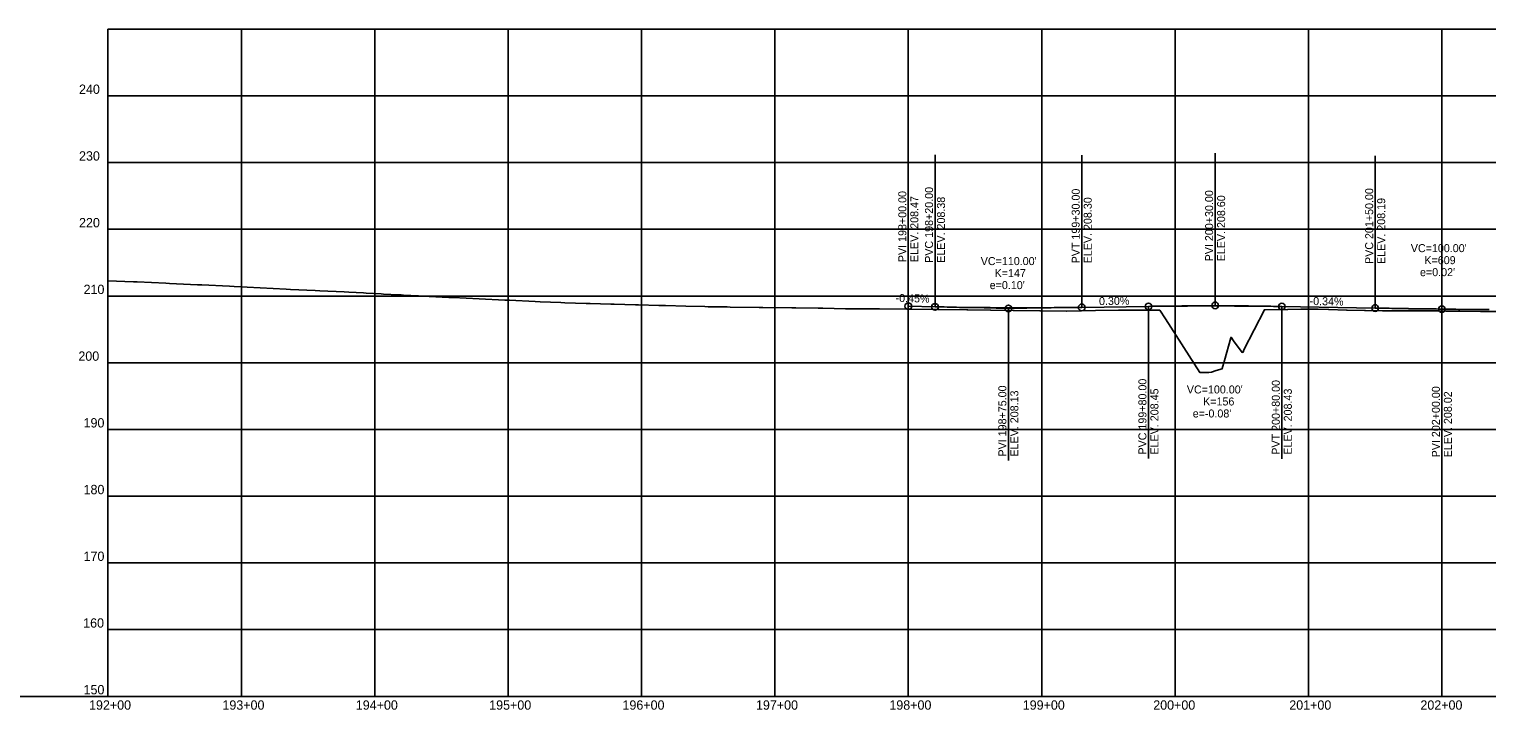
# Model space of a CAD drawing. Extents: x 1138442 to 1165793, y 1654070 to 1657687.
# Drawn here: x 1148047 to 1149139, y 1655756 to 1656266 of the extents above; entities that cross this region are included whole.
import ezdxf

# ---------------------------------------------------------------- set-up
doc = ezdxf.new("R2010")
doc.units = 0
for name, color, linetype in [('B_Dimensions', 7, 'Continuous'), ('R_Axis', 7, 'Continuous'), ('R_Axis Annot', 7, 'Continuous'), ('R_Grid', 7, 'Continuous'), ('R_No Plot', 7, 'Continuous'), ('R_Proposed Const Limits_Hand', 7, 'Continuous'), ('R_Vert Alg Annot', 7, 'Continuous')]:
    doc.layers.add(name, color=color, linetype=linetype)

msp = doc.modelspace()

# ---------------------------------------------------------------- linework, layer by layer
at = {"layer": 'B_Dimensions'}
for p, q in [((1148705.7, 1656058.8), (1148725.7, 1656058.3)), ((1148753.2, 1656057.7), (1148780.7, 1656057.1)), ((1148780.7, 1656057.1), (1148808.2, 1656057.5)), ((1148835.7, 1656057.9), (1148885.7, 1656058.6)), ((1148910.7, 1656059), (1148935.7, 1656059.4)), ((1148935.7, 1656059.4), (1148960.7, 1656059)), ((1148985.7, 1656058.5), (1149055.7, 1656057.4)), ((1149080.7, 1656056.9), (1149105.7, 1656056.5)), ((1149105.7, 1656056.5), (1149130.7, 1656056.3))]:
    msp.add_line(p, q, dxfattribs=at)
for points in [[(1148725.7, 1656058.3), (1148728, 1656058.3), (1148730.3, 1656058.2), (1148732.6, 1656058.2), (1148734.9, 1656058.1), (1148737.2, 1656058.1), (1148739.5, 1656058), (1148741.7, 1656058), (1148744, 1656057.9), (1148746.3, 1656057.9), (1148748.6, 1656057.9), (1148750.9, 1656057.8), (1148753.2, 1656057.8), (1148755.5, 1656057.8), (1148757.8, 1656057.8), (1148760.1, 1656057.7), (1148762.4, 1656057.7), (1148764.7, 1656057.7), (1148767, 1656057.7), (1148769.2, 1656057.6), (1148771.5, 1656057.6), (1148773.8, 1656057.6), (1148776.1, 1656057.6), (1148778.4, 1656057.6), (1148783, 1656057.6), (1148785.3, 1656057.6), (1148787.6, 1656057.6), (1148789.9, 1656057.6), (1148792.2, 1656057.6), (1148794.5, 1656057.6), (1148796.7, 1656057.6), (1148799, 1656057.6), (1148801.3, 1656057.6), (1148803.6, 1656057.6), (1148805.9, 1656057.6), (1148808.2, 1656057.6), (1148810.5, 1656057.6), (1148812.8, 1656057.6), (1148815.1, 1656057.7), (1148817.4, 1656057.7), (1148819.7, 1656057.7), (1148822, 1656057.7), (1148824.2, 1656057.7), (1148826.5, 1656057.8), (1148828.8, 1656057.8), (1148831.1, 1656057.8), (1148833.4, 1656057.9), (1148835.7, 1656057.9)], [(1148885.7, 1656058.6), (1148887.8, 1656058.7), (1148889.9, 1656058.7), (1148892, 1656058.7), (1148894, 1656058.8), (1148896.1, 1656058.8), (1148898.2, 1656058.8), (1148900.3, 1656058.8), (1148902.4, 1656058.8), (1148904.5, 1656058.9), (1148906.5, 1656058.9), (1148908.6, 1656058.9), (1148910.7, 1656058.9), (1148912.8, 1656058.9), (1148914.9, 1656058.9), (1148917, 1656059), (1148919, 1656059), (1148921.1, 1656059), (1148923.2, 1656059), (1148925.3, 1656059), (1148927.4, 1656059), (1148929.5, 1656059), (1148931.5, 1656059), (1148933.6, 1656059), (1148937.8, 1656059), (1148939.9, 1656059), (1148942, 1656059), (1148944, 1656059), (1148946.1, 1656059), (1148948.2, 1656059), (1148950.3, 1656058.9), (1148952.4, 1656058.9), (1148954.5, 1656058.9), (1148956.5, 1656058.9), (1148958.6, 1656058.9), (1148960.7, 1656058.9), (1148962.8, 1656058.8), (1148964.9, 1656058.8), (1148967, 1656058.8), (1148969, 1656058.8), (1148971.1, 1656058.8), (1148973.2, 1656058.7), (1148975.3, 1656058.7), (1148977.4, 1656058.7), (1148979.5, 1656058.6), (1148981.5, 1656058.6), (1148983.6, 1656058.6), (1148985.7, 1656058.5)], [(1149055.7, 1656057.4), (1149057.8, 1656057.3), (1149059.9, 1656057.3), (1149062, 1656057.2), (1149064, 1656057.2), (1149066.1, 1656057.2), (1149068.2, 1656057.1), (1149070.3, 1656057.1), (1149072.4, 1656057.1), (1149074.5, 1656057), (1149076.5, 1656057), (1149078.6, 1656057), (1149080.7, 1656057), (1149082.8, 1656056.9), (1149084.9, 1656056.9), (1149087, 1656056.9), (1149089, 1656056.8), (1149091.1, 1656056.8), (1149093.2, 1656056.8), (1149095.3, 1656056.7), (1149097.4, 1656056.7), (1149099.5, 1656056.7), (1149101.5, 1656056.7), (1149103.6, 1656056.6), (1149107.8, 1656056.6), (1149109.9, 1656056.6), (1149112, 1656056.5), (1149114, 1656056.5), (1149116.1, 1656056.5), (1149118.2, 1656056.4), (1149120.3, 1656056.4), (1149122.4, 1656056.4), (1149124.5, 1656056.4), (1149126.5, 1656056.4), (1149128.6, 1656056.3), (1149130.7, 1656056.3), (1149132.8, 1656056.3), (1149134.9, 1656056.3), (1149137, 1656056.2), (1149139, 1656056.2), (1149141.1, 1656056.2)]]:
    msp.add_lwpolyline(points, dxfattribs=at)
at = {"layer": 'R_Axis'}
for q in [(1148105.7, 1656266.4), (1149805.7, 1655766.4)]:
    msp.add_line((1148105.7, 1655766.4), q, dxfattribs=at)
at = {"layer": 'R_Grid'}
for p, q in [((1148105.7, 1656266.4), (1149805.7, 1656266.4)), ((1148105.7, 1656266.4), (1149805.7, 1656266.4)), ((1148205.7, 1655766.4), (1148205.7, 1656266.4)), ((1148305.7, 1655766.4), (1148305.7, 1656266.4)), ((1148405.7, 1655766.4), (1148405.7, 1656266.4)), ((1148505.7, 1655766.4), (1148505.7, 1656266.4)), ((1148605.7, 1655766.4), (1148605.7, 1656266.4)), ((1148705.7, 1655766.4), (1148705.7, 1656266.4)), ((1148805.7, 1655766.4), (1148805.7, 1656266.4)), ((1148905.7, 1655766.4), (1148905.7, 1656266.4)), ((1149005.7, 1655766.4), (1149005.7, 1656266.4)), ((1149105.7, 1655766.4), (1149105.7, 1656266.4)), ((1148105.7, 1656216.4), (1149805.7, 1656216.4)), ((1148105.7, 1656166.4), (1149805.7, 1656166.4)), ((1148105.7, 1656116.4), (1149805.7, 1656116.4)), ((1148105.7, 1656066.4), (1149805.7, 1656066.4)), ((1148105.7, 1656016.4), (1149805.7, 1656016.4)), ((1148105.7, 1655966.4), (1149805.7, 1655966.4)), ((1148105.7, 1655916.4), (1149805.7, 1655916.4)), ((1148105.7, 1655866.4), (1149805.7, 1655866.4)), ((1148105.7, 1655816.4), (1149805.7, 1655816.4))]:
    msp.add_line(p, q, dxfattribs=at)
at = {"layer": 'R_No Plot'}
msp.add_line((1148105.7, 1655766.4), (1146536.5, 1655766.4), dxfattribs=at)
at = {"layer": 'R_Proposed Const Limits_Hand'}
msp.add_lwpolyline([(1148105.7, 1656077.9), (1148124.8, 1656077.1), (1148127.7, 1656077), (1148149, 1656076), (1148151.7, 1656075.9), (1148172.9, 1656074.9), (1148176, 1656074.8), (1148196.9, 1656073.8), (1148200.4, 1656073.6), (1148219.7, 1656072.5), (1148239.3, 1656071.5), (1148242.5, 1656071.3), (1148261.1, 1656070.5), (1148264.4, 1656070.3), (1148282.7, 1656069.5), (1148286.3, 1656069.3), (1148297.3, 1656068.7), (1148299.3, 1656068.6), (1148310.4, 1656068), (1148312.3, 1656067.9), (1148323.5, 1656067.3), (1148325.4, 1656067.2), (1148327.3, 1656067.1), (1148338.4, 1656066.5), (1148341.6, 1656066.4), (1148361.2, 1656065.4), (1148364.5, 1656065.3), (1148384, 1656064.3), (1148403.3, 1656063.4), (1148406.8, 1656063.2), (1148426, 1656062.3), (1148429.6, 1656062.1), (1148445.3, 1656061.6), (1148448.3, 1656061.4), (1148464.1, 1656060.9), (1148467.1, 1656060.8), (1148482.8, 1656060.3), (1148485.2, 1656060.2), (1148501.2, 1656059.8), (1148503.3, 1656059.7), (1148518.7, 1656059.3), (1148521.2, 1656059.2), (1148523.6, 1656059.2), (1148539, 1656058.7), (1148553.1, 1656058.5), (1148555.6, 1656058.4), (1148570, 1656058.2), (1148572.1, 1656058.1), (1148593.8, 1656057.8), (1148596.7, 1656057.8), (1148618.4, 1656057.5), (1148621.3, 1656057.5), (1148638.2, 1656057.2), (1148640, 1656057.2), (1148641.7, 1656057.2), (1148658.7, 1656056.9), (1148659.6, 1656056.9), (1148682.3, 1656056.8), (1148683.1, 1656056.8), (1148684, 1656056.8), (1148706.7, 1656056.6), (1148707.6, 1656056.6), (1148727.8, 1656056.3), (1148728.9, 1656056.3), (1148749.5, 1656056), (1148750.2, 1656056), (1148767.2, 1656055.8), (1148767.2, 1656055.8), (1148767.5, 1656055.8), (1148784.4, 1656055.5), (1148785, 1656055.5), (1148804.3, 1656055.3), (1148804.8, 1656055.3), (1148824.2, 1656055.1), (1148824.6, 1656055.1), (1148845.9, 1656055.5), (1148846.1, 1656055.5), (1148863.3, 1656055.7), (1148867.6, 1656055.8), (1148867.6, 1656055.8), (1148880.8, 1656055.9), (1148880.9, 1656055.9), (1148894.1, 1656055.9), (1148894.1, 1656055.9), (1148894.2, 1656055.9), (1148898.5, 1656049.2), (1148924.3, 1656009.1), (1148924.4, 1656009.1), (1148931, 1656009.2), (1148933, 1656009.3), (1148933, 1656009.3), (1148936.6, 1656010.5), (1148941.1, 1656011.9), (1148941.1, 1656012), (1148942.8, 1656018), (1148947.6, 1656035), (1148947.7, 1656035.5), (1148949.4, 1656032.9), (1148955.9, 1656024.1), (1148956.7, 1656024.4), (1148957.2, 1656026.2), (1148972.6, 1656056.1), (1148972.7, 1656056.1), (1148973.2, 1656056.1), (1148990, 1656056.4), (1148990.2, 1656056.4), (1148999.9, 1656056.5), (1149007.3, 1656056.6), (1149007.4, 1656056.6), (1149012.9, 1656056.5), (1149020.7, 1656056.3), (1149021, 1656056.3), (1149034.2, 1656055.9), (1149034.7, 1656055.9), (1149047.7, 1656055.6), (1149048.5, 1656055.6), (1149061.3, 1656055.3), (1149081.4, 1656055.2), (1149082.2, 1656055.2), (1149083, 1656055.2), (1149103.1, 1656055.2), (1149103.2, 1656055.2), (1149108.6, 1656055.1), (1149118.9, 1656055), (1149119.1, 1656055), (1149134.6, 1656054.9), (1149135.1, 1656054.9), (1149150.4, 1656054.8)], dxfattribs=at)
at = {"layer": 'R_Vert Alg Annot'}
for p, q in [((1148705.7, 1656088.8), (1148705.7, 1656172.8)), ((1148725.7, 1656088.3), (1148725.7, 1656172.3)), ((1148835.7, 1656087.9), (1148835.7, 1656171.9)), ((1148935.7, 1656089.4), (1148935.7, 1656173.4)), ((1149055.7, 1656087.4), (1149055.7, 1656171.4)), ((1148705.7, 1656058.8), (1148705.7, 1656088.8)), ((1148725.7, 1656058.3), (1148725.7, 1656088.3)), ((1148835.7, 1656057.9), (1148835.7, 1656087.9)), ((1148935.7, 1656059.4), (1148935.7, 1656089.4)), ((1149055.7, 1656057.4), (1149055.7, 1656087.4)), ((1148780.7, 1656057.1), (1148780.7, 1656027.1)), ((1148885.7, 1656058.6), (1148885.7, 1656028.6)), ((1148985.7, 1656058.5), (1148985.7, 1656028.5)), ((1149105.7, 1656056.5), (1149105.7, 1656026.5)), ((1148780.7, 1656027.1), (1148780.7, 1655943.1)), ((1148885.7, 1656028.6), (1148885.7, 1655944.6)), ((1148985.7, 1656028.5), (1148985.7, 1655944.5)), ((1149105.7, 1656026.5), (1149105.7, 1655942.5))]:
    msp.add_line(p, q, dxfattribs=at)
for centre in [(1148935.7, 1656059.4), (1148705.7, 1656058.8), (1148725.7, 1656058.3), (1148780.7, 1656057.1), (1148835.7, 1656057.9), (1148885.7, 1656058.6), (1148985.7, 1656058.5), (1149055.7, 1656057.4), (1149105.7, 1656056.5)]:
    msp.add_circle(centre, 2.5, dxfattribs=at)

# ---------------------------------------------------------------- texts
at = {"layer": 'R_Axis Annot'}
for s, height, p in [('240', 7, (1148084, 1656217.9)), ('230', 7, (1148084, 1656167.9)), ('220', 7, (1148084, 1656117.9)), ('210', 7, (1148087.4, 1656067.9)), ('200', 7, (1148083.5, 1656017.9)), ('190', 7, (1148087.4, 1655967.9)), ('180', 7, (1148087.4, 1655917.9)), ('170', 7, (1148087.4, 1655867.9)), ('160', 7, (1148087.1, 1655817.9)), ('150', 7, (1148087.4, 1655767.9)), ('192+00', 7, (1148091.5, 1655756.4)), ('-', 0.0001, (1148105.7, 1655766.4)), ('193+00', 7, (1148191.5, 1655756.4)), ('194+00', 7, (1148291.5, 1655756.4)), ('195+00', 7, (1148391.5, 1655756.4)), ('196+00', 7, (1148491.4, 1655756.4)), ('197+00', 7, (1148591.5, 1655756.4)), ('198+00', 7, (1148691.5, 1655756.4)), ('199+00', 7, (1148791.5, 1655756.4)), ('200+00', 7, (1148889.3, 1655756.4)), ('201+00', 7, (1148991.3, 1655756.4)), ('202+00', 7, (1149089.6, 1655756.4))]:
    msp.add_text(s, height=height, dxfattribs=at).set_placement(p)
at = {"layer": 'R_Vert Alg Annot'}
for s, rotation, p in [('PVI 198+00.00', 90, (1148704.2, 1656091.8)), ('ELEV. 208.47', 90, (1148713.2, 1656091.8)), ('PVC 198+20.00', 90, (1148724.2, 1656091.3)), ('ELEV. 208.38', 90, (1148733.2, 1656091.3)), ('PVT 199+30.00', 90, (1148834.2, 1656090.9)), ('ELEV. 208.30', 90, (1148843.2, 1656090.9)), ('PVI 200+30.00', 90, (1148934.2, 1656092.4)), ('ELEV. 208.60', 90, (1148943.2, 1656092.4)), ('PVC 201+50.00', 90, (1149054.2, 1656090.4)), ('ELEV. 208.19', 90, (1149063.2, 1656090.4)), ('-0.45%', 358.7111, (1148696.1, 1656062)), ('0.30%', 0.8594, (1148848.7, 1656059.6)), ('-0.34%', 359.0261, (1149006.5, 1656059.7)), ('PVI 198+75.00', 90, (1148779.2, 1655946.1)), ('PVC 199+80.00', 90, (1148884.2, 1655947.6)), ('ELEV. 208.45', 90, (1148893.2, 1655947.6)), ('PVT 200+80.00', 90, (1148984.2, 1655947.5)), ('ELEV. 208.43', 90, (1148993.2, 1655947.5)), ('PVI 202+00.00', 90, (1149104.2, 1655945.5)), ('ELEV. 208.13', 90, (1148788.2, 1655946.1)), ('ELEV. 208.02', 90, (1149113.2, 1655945.5))]:
    msp.add_text(s, height=6, rotation=rotation, dxfattribs=at).set_placement(p)
for s, p in [("VC=110.00'", (1148760, 1656089.6)), ("VC=100.00'", (1149082.4, 1656099.3)), ('K=609', (1149092.6, 1656090.3)), ('K=147', (1148770.4, 1656080.6)), ("e=0.02'", (1149089.3, 1656081.3)), ("e=0.10'", (1148766.7, 1656071.6)), ("VC=100.00'", (1148914.5, 1655993.4)), ('K=156', (1148926.7, 1655984.4)), ("e=-0.08'", (1148918.9, 1655975.4))]:
    msp.add_text(s, height=6, dxfattribs=at).set_placement(p)

doc.saveas('drawing.dxf')
